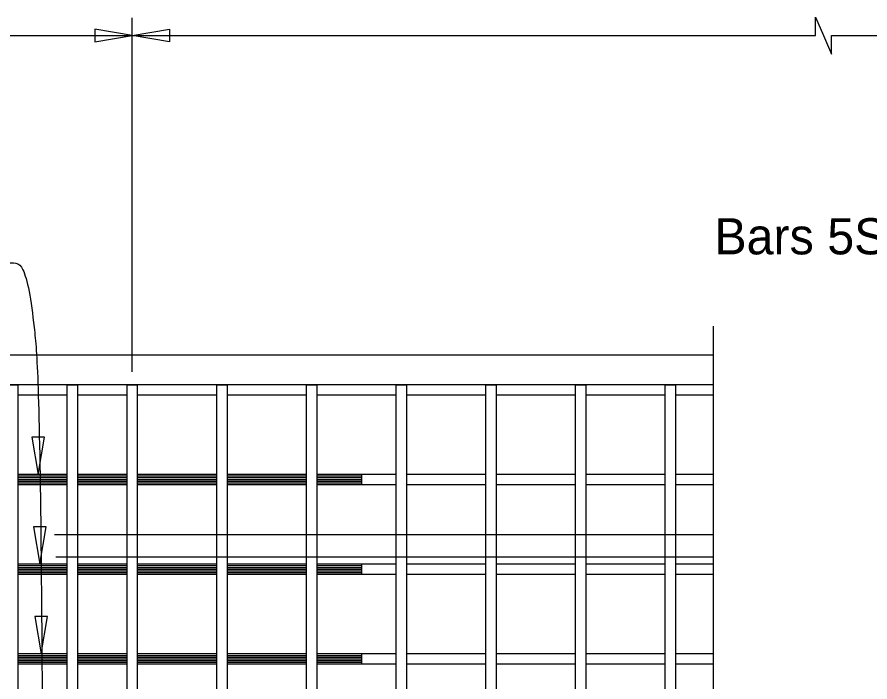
# Model space of a CAD drawing. Extents: x 120588.1 to 120659.6, y 120683.4 to 120715.5.
# Drawn here: x 120603.786 to 120608.54, y 120702.598 to 120706.304 of the extents above; entities that cross this region are included whole.
import ezdxf

# ---------------------------------------------------------------- set-up
doc = ezdxf.new("R2010")
doc.units = 0
for name, color, linetype in [('Patterning', 7, 'Continuous'), ('SheetBorder_dp', 7, 'Continuous'), ('SheetLines_dp', 7, 'Continuous'), ('SupstrConc', 7, 'Continuous')]:
    doc.layers.add(name, color=color, linetype=linetype)

msp = doc.modelspace()

# ---------------------------------------------------------------- linework, layer by layer
at = {"layer": 'SheetBorder_dp'}
for p, q in [((120598.1865, 120704.4203), (120607.6672, 120704.4203)), ((120603.9947, 120703.4203), (120607.6672, 120703.4203)), ((120604.0015, 120703.2953), (120607.6672, 120703.2953))]:
    msp.add_line(p, q, dxfattribs=at)
at = {"layer": 'SheetLines_dp'}
for p, q in [((120604.4273, 120704.3267), (120604.4273, 120706.3004)), ((120588.2204, 120706.2005), (120604.4273, 120706.2005))]:
    msp.add_line(p, q, dxfattribs=at)
for points in [[(120604.4273, 120706.2005), (120608.2363, 120706.2005), (120608.2363, 120706.3038), (120608.2812, 120706.2005), (120608.3262, 120706.0971), (120608.3262, 120706.2005), (120610.2647, 120706.2005)], [(120607.6672, 120699.087), (120607.6672, 120701.3501), (120607.5639, 120701.3501), (120607.6672, 120701.3951), (120607.7706, 120701.4401), (120607.6672, 120701.4401), (120607.6672, 120704.5808)]]:
    msp.add_lwpolyline(points, dxfattribs=at)
for points in [[(120604.4273, 120706.2005), (120604.2191, 120706.2358), (120604.2191, 120706.1652)], [(120604.4273, 120706.2005), (120604.6356, 120706.2358), (120604.6356, 120706.1652)], [(120603.9027, 120703.7537), (120603.938, 120703.962), (120603.8675, 120703.962)], [(120603.9128, 120703.2537), (120603.9481, 120703.462), (120603.8776, 120703.462)], [(120603.9193, 120702.7537), (120603.9546, 120702.962), (120603.884, 120702.962)]]:
    msp.add_lwpolyline(points, close=True, dxfattribs=at)
msp.add_open_spline([(120603.5625, 120704.9329), (120603.7055, 120704.9329), (120603.8544, 120704.9329), (120603.9319, 120703.9432), (120603.9317, 120699.7537)], degree=2, dxfattribs=at)
at = {"layer": 'SupstrConc'}
for p, q in [((120607.6672, 120704.2537), (120598.2907, 120704.2537)), ((120604.0653, 120704.1964), (120603.7893, 120704.1964)), ((120604.3987, 120704.1964), (120604.1226, 120704.1964)), ((120604.8987, 120704.1964), (120604.456, 120704.1964)), ((120605.3987, 120704.1964), (120604.956, 120704.1964)), ((120605.8987, 120704.1964), (120605.456, 120704.1964)), ((120606.3987, 120704.1964), (120605.956, 120704.1964)), ((120606.8987, 120704.1964), (120606.456, 120704.1964)), ((120607.3987, 120704.1964), (120606.956, 120704.1964)), ((120607.6672, 120704.1964), (120607.456, 120704.1964)), ((120604.0653, 120703.7537), (120603.7893, 120703.7537)), ((120604.0653, 120703.7442), (120603.7893, 120703.7442)), ((120604.0653, 120703.7346), (120603.7893, 120703.7346)), ((120604.0653, 120703.7251), (120603.7893, 120703.7251)), ((120604.0653, 120703.7155), (120603.7893, 120703.7155)), ((120604.3987, 120703.7537), (120604.1226, 120703.7537)), ((120604.3987, 120703.7442), (120604.1226, 120703.7442)), ((120604.3987, 120703.7346), (120604.1226, 120703.7346)), ((120604.3987, 120703.7251), (120604.1226, 120703.7251)), ((120604.3987, 120703.7155), (120604.1226, 120703.7155)), ((120604.8987, 120703.7537), (120604.456, 120703.7537)), ((120604.8987, 120703.7442), (120604.456, 120703.7442)), ((120604.8987, 120703.7346), (120604.456, 120703.7346)), ((120604.8987, 120703.7251), (120604.456, 120703.7251)), ((120604.8987, 120703.7155), (120604.456, 120703.7155)), ((120605.3987, 120703.7537), (120604.956, 120703.7537)), ((120605.3987, 120703.7442), (120604.956, 120703.7442)), ((120605.3987, 120703.7346), (120604.956, 120703.7346)), ((120605.3987, 120703.7251), (120604.956, 120703.7251)), ((120605.3987, 120703.7155), (120604.956, 120703.7155)), ((120605.8987, 120703.7537), (120605.456, 120703.7537)), ((120605.706, 120703.7442), (120605.456, 120703.7442)), ((120605.706, 120703.7346), (120605.456, 120703.7346)), ((120605.706, 120703.7251), (120605.456, 120703.7251)), ((120605.706, 120703.7155), (120605.456, 120703.7155)), ((120605.706, 120703.7537), (120605.706, 120703.6964)), ((120606.3987, 120703.7537), (120605.956, 120703.7537)), ((120606.8987, 120703.7537), (120606.456, 120703.7537)), ((120607.3987, 120703.7537), (120606.956, 120703.7537)), ((120607.6672, 120703.7537), (120607.456, 120703.7537)), ((120604.0653, 120703.706), (120603.7893, 120703.706)), ((120604.0653, 120703.6964), (120603.7893, 120703.6964)), ((120604.3987, 120703.706), (120604.1226, 120703.706)), ((120604.3987, 120703.6964), (120604.1226, 120703.6964)), ((120604.8987, 120703.706), (120604.456, 120703.706)), ((120604.8987, 120703.6964), (120604.456, 120703.6964)), ((120605.3987, 120703.706), (120604.956, 120703.706)), ((120605.3987, 120703.6964), (120604.956, 120703.6964)), ((120605.706, 120703.706), (120605.456, 120703.706)), ((120605.8987, 120703.6964), (120605.456, 120703.6964)), ((120606.3987, 120703.6964), (120605.956, 120703.6964)), ((120606.8987, 120703.6964), (120606.456, 120703.6964)), ((120607.3987, 120703.6964), (120606.956, 120703.6964)), ((120607.6672, 120703.6964), (120607.456, 120703.6964)), ((120604.0653, 120703.2537), (120603.7893, 120703.2537)), ((120604.0653, 120703.2442), (120603.7893, 120703.2442)), ((120604.3987, 120703.2537), (120604.1226, 120703.2537)), ((120604.3987, 120703.2442), (120604.1226, 120703.2442)), ((120604.8987, 120703.2537), (120604.456, 120703.2537)), ((120604.8987, 120703.2442), (120604.456, 120703.2442)), ((120605.3987, 120703.2537), (120604.956, 120703.2537)), ((120605.3987, 120703.2442), (120604.956, 120703.2442)), ((120605.8987, 120703.2537), (120605.456, 120703.2537)), ((120605.706, 120703.2442), (120605.456, 120703.2442)), ((120605.706, 120703.2537), (120605.706, 120703.1964)), ((120606.3987, 120703.2537), (120605.956, 120703.2537)), ((120606.8987, 120703.2537), (120606.456, 120703.2537)), ((120607.3987, 120703.2537), (120606.956, 120703.2537)), ((120607.6672, 120703.2537), (120607.456, 120703.2537)), ((120604.0653, 120703.2346), (120603.7893, 120703.2346)), ((120604.0653, 120703.2251), (120603.7893, 120703.2251)), ((120604.0653, 120703.2155), (120603.7893, 120703.2155)), ((120604.0653, 120703.206), (120603.7893, 120703.206)), ((120604.0653, 120703.1964), (120603.7893, 120703.1964)), ((120604.3987, 120703.2346), (120604.1226, 120703.2346)), ((120604.3987, 120703.2251), (120604.1226, 120703.2251)), ((120604.3987, 120703.2155), (120604.1226, 120703.2155)), ((120604.3987, 120703.206), (120604.1226, 120703.206)), ((120604.3987, 120703.1964), (120604.1226, 120703.1964)), ((120604.8987, 120703.2346), (120604.456, 120703.2346)), ((120604.8987, 120703.2251), (120604.456, 120703.2251)), ((120604.8987, 120703.2155), (120604.456, 120703.2155)), ((120604.8987, 120703.206), (120604.456, 120703.206)), ((120604.8987, 120703.1964), (120604.456, 120703.1964)), ((120605.3987, 120703.2346), (120604.956, 120703.2346)), ((120605.3987, 120703.2251), (120604.956, 120703.2251)), ((120605.3987, 120703.2155), (120604.956, 120703.2155)), ((120605.3987, 120703.206), (120604.956, 120703.206)), ((120605.3987, 120703.1964), (120604.956, 120703.1964)), ((120605.706, 120703.2346), (120605.456, 120703.2346)), ((120605.706, 120703.2251), (120605.456, 120703.2251)), ((120605.706, 120703.2155), (120605.456, 120703.2155)), ((120605.706, 120703.206), (120605.456, 120703.206)), ((120605.8987, 120703.1964), (120605.456, 120703.1964)), ((120606.3987, 120703.1964), (120605.956, 120703.1964)), ((120606.8987, 120703.1964), (120606.456, 120703.1964)), ((120607.3987, 120703.1964), (120606.956, 120703.1964)), ((120607.6672, 120703.1964), (120607.456, 120703.1964)), ((120604.0653, 120702.7537), (120603.7893, 120702.7537)), ((120604.0653, 120702.7442), (120603.7893, 120702.7442)), ((120604.0653, 120702.7346), (120603.7893, 120702.7346)), ((120604.0653, 120702.7251), (120603.7893, 120702.7251)), ((120604.3987, 120702.7537), (120604.1226, 120702.7537)), ((120604.3987, 120702.7442), (120604.1226, 120702.7442)), ((120604.3987, 120702.7346), (120604.1226, 120702.7346)), ((120604.3987, 120702.7251), (120604.1226, 120702.7251)), ((120604.8987, 120702.7537), (120604.456, 120702.7537)), ((120604.8987, 120702.7442), (120604.456, 120702.7442)), ((120604.8987, 120702.7346), (120604.456, 120702.7346)), ((120604.8987, 120702.7251), (120604.456, 120702.7251)), ((120605.3987, 120702.7537), (120604.956, 120702.7537)), ((120605.3987, 120702.7442), (120604.956, 120702.7442)), ((120605.3987, 120702.7346), (120604.956, 120702.7346)), ((120605.3987, 120702.7251), (120604.956, 120702.7251)), ((120605.8987, 120702.7537), (120605.456, 120702.7537)), ((120605.706, 120702.7442), (120605.456, 120702.7442)), ((120605.706, 120702.7346), (120605.456, 120702.7346)), ((120605.706, 120702.7251), (120605.456, 120702.7251)), ((120605.706, 120702.7537), (120605.706, 120702.6964)), ((120606.3987, 120702.7537), (120605.956, 120702.7537)), ((120606.8987, 120702.7537), (120606.456, 120702.7537)), ((120607.3987, 120702.7537), (120606.956, 120702.7537)), ((120607.6672, 120702.7537), (120607.456, 120702.7537)), ((120604.0653, 120702.7155), (120603.7893, 120702.7155)), ((120604.0653, 120702.706), (120603.7893, 120702.706)), ((120604.0653, 120702.6964), (120603.7893, 120702.6964)), ((120604.3987, 120702.7155), (120604.1226, 120702.7155)), ((120604.3987, 120702.706), (120604.1226, 120702.706)), ((120604.3987, 120702.6964), (120604.1226, 120702.6964)), ((120604.8987, 120702.7155), (120604.456, 120702.7155)), ((120604.8987, 120702.706), (120604.456, 120702.706)), ((120604.8987, 120702.6964), (120604.456, 120702.6964)), ((120605.3987, 120702.7155), (120604.956, 120702.7155)), ((120605.3987, 120702.706), (120604.956, 120702.706)), ((120605.3987, 120702.6964), (120604.956, 120702.6964)), ((120605.706, 120702.7155), (120605.456, 120702.7155)), ((120605.706, 120702.706), (120605.456, 120702.706)), ((120605.8987, 120702.6964), (120605.456, 120702.6964)), ((120606.3987, 120702.6964), (120605.956, 120702.6964)), ((120606.8987, 120702.6964), (120606.456, 120702.6964)), ((120607.3987, 120702.6964), (120606.956, 120702.6964)), ((120607.6672, 120702.6964), (120607.456, 120702.6964))]:
    msp.add_line(p, q, dxfattribs=at)
for points in [[(120603.732, 120704.2537), (120603.7893, 120704.2537), (120603.7893, 120696.587), (120603.732, 120696.587)], [(120604.0653, 120704.2537), (120604.1226, 120704.2537), (120604.1226, 120696.587), (120604.0653, 120696.587)], [(120604.3987, 120704.2537), (120604.456, 120704.2537), (120604.456, 120696.587), (120604.3987, 120696.587)], [(120604.8987, 120704.2537), (120604.956, 120704.2537), (120604.956, 120696.587), (120604.8987, 120696.587)], [(120605.8987, 120704.2537), (120605.956, 120704.2537), (120605.956, 120696.587), (120605.8987, 120696.587)], [(120606.3987, 120704.2537), (120606.456, 120704.2537), (120606.456, 120696.587), (120606.3987, 120696.587)], [(120606.8987, 120704.2537), (120606.956, 120704.2537), (120606.956, 120696.587), (120606.8987, 120696.587)], [(120607.3987, 120704.2537), (120607.456, 120704.2537), (120607.456, 120696.587), (120607.3987, 120696.587)]]:
    msp.add_lwpolyline(points, close=True, dxfattribs=at)
msp.add_lwpolyline([(120605.456, 120696.587), (120605.3987, 120696.587), (120605.3987, 120704.2537), (120605.456, 120704.2537), (120605.456, 120696.587)], dxfattribs=at)

# ---------------------------------------------------------------- texts
at = {"layer": 'Patterning'}
msp.add_text('Bars 5S1 *', height=0.2016, dxfattribs=at).set_placement((120607.6725, 120704.9811))

doc.saveas('drawing.dxf')
